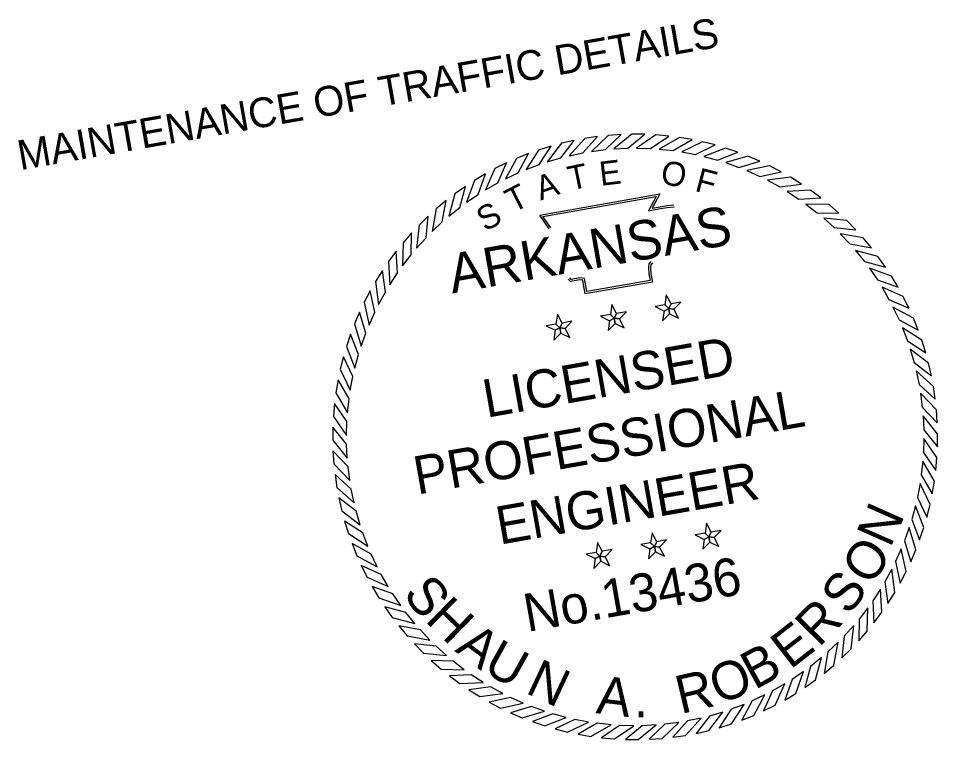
# Model space of a CAD drawing. Extents: x 986385 to 987873, y 1837463 to 1838653.
# Drawn here: x 987580 to 987761.3, y 1838510.4 to 1838652.5 of the extents above; entities that cross this region are included whole.
import ezdxf

# ---------------------------------------------------------------- set-up
doc = ezdxf.new("R2010")
doc.units = 0
doc.layers.add('1', color=7, linetype='Continuous')
doc.layers.add('G-ANNO-SYMB', color=7, linetype='Continuous')

msp = doc.modelspace()

# ---------------------------------------------------------------- linework, layer by layer
at = {"layer": 'G-ANNO-SYMB'}
for points in [[(987694.25, 1838629.23), (987691.71, 1838628.85), (987688.65, 1838625.45), (987691.37, 1838626.02)], [(987698.92, 1838629.62), (987696.36, 1838629.45), (987693.04, 1838626.3), (987695.79, 1838626.66)], [(987703.6, 1838629.66), (987701.04, 1838629.68), (987697.48, 1838626.81), (987700.25, 1838626.94)], [(987708.28, 1838629.32), (987705.72, 1838629.55), (987701.95, 1838626.96), (987704.72, 1838626.88)], [(987712.91, 1838628.62), (987710.38, 1838629.05), (987706.42, 1838626.76), (987709.17, 1838626.46)], [(987685.08, 1838627.34), (987682.63, 1838626.57), (987680.14, 1838622.74), (987682.73, 1838623.72)], [(987689.63, 1838628.46), (987687.13, 1838627.89), (987684.34, 1838624.26), (987687, 1838625.04)], [(987717.47, 1838627.56), (987714.98, 1838628.18), (987710.85, 1838626.21), (987713.58, 1838625.7)], [(987721.93, 1838626.14), (987719.5, 1838626.96), (987715.23, 1838625.32), (987717.91, 1838624.59)], [(987680.64, 1838625.86), (987678.26, 1838624.9), (987676.07, 1838620.88), (987678.58, 1838622.07)], [(987726.27, 1838624.38), (987723.91, 1838625.38), (987719.53, 1838624.08), (987722.14, 1838623.15)], [(987676.32, 1838624.04), (987674.02, 1838622.9), (987672.16, 1838618.72), (987674.57, 1838620.1)], [(987730.46, 1838622.28), (987728.19, 1838623.47), (987723.72, 1838622.52), (987726.24, 1838621.38)], [(987672.16, 1838621.88), (987669.96, 1838620.57), (987668.43, 1838616.26), (987670.72, 1838617.82)], [(987734.47, 1838619.86), (987732.3, 1838621.22), (987727.77, 1838620.62), (987730.2, 1838619.29)], [(987668.18, 1838619.41), (987666.09, 1838617.92), (987664.91, 1838613.51), (987667.07, 1838615.24)], [(987738.28, 1838617.13), (987736.22, 1838618.66), (987731.66, 1838618.42), (987733.98, 1838616.9)], [(987664.41, 1838616.63), (987662.44, 1838614.98), (987661.61, 1838610.49), (987663.63, 1838612.39)], [(987741.86, 1838614.11), (987739.93, 1838615.8), (987735.36, 1838615.92), (987737.55, 1838614.22)], [(987660.87, 1838613.56), (987659.04, 1838611.77), (987658.56, 1838607.22), (987660.42, 1838609.27)], [(987745.2, 1838610.82), (987743.4, 1838612.65), (987738.86, 1838613.13), (987740.91, 1838611.27)], [(987657.58, 1838610.23), (987655.89, 1838608.3), (987655.77, 1838603.72), (987657.47, 1838605.92)], [(987748.26, 1838607.28), (987746.62, 1838609.25), (987742.12, 1838610.08), (987744.03, 1838608.06)], [(987751.04, 1838603.51), (987749.56, 1838605.6), (987745.14, 1838606.78), (987746.88, 1838604.62)], [(987654.56, 1838606.65), (987653.03, 1838604.59), (987653.27, 1838600.02), (987654.79, 1838602.34)], [(987753.52, 1838599.53), (987752.2, 1838601.73), (987747.89, 1838603.26), (987749.45, 1838600.97)], [(987651.84, 1838602.84), (987650.47, 1838600.66), (987651.07, 1838596.13), (987652.4, 1838598.56)], [(987755.67, 1838595.37), (987754.53, 1838597.67), (987750.36, 1838599.53), (987751.73, 1838597.12)], [(987649.42, 1838598.83), (987648.23, 1838596.55), (987649.18, 1838592.08), (987650.31, 1838594.61)], [(987708.28, 1838595.32), (987708.74, 1838596.25), (987707.81, 1838598), (987707.53, 1838596.04)], [(987697.54, 1838593.42), (987698, 1838594.36), (987697.07, 1838596.11), (987696.79, 1838594.15)], [(987708.28, 1838595.32), (987707.53, 1838596.04), (987705.58, 1838595.7), (987707.36, 1838594.83)], [(987708.28, 1838595.32), (987709.31, 1838595.17), (987710.69, 1838596.6), (987708.74, 1838596.25)], [(987647.32, 1838594.64), (987646.31, 1838592.28), (987647.61, 1838587.89), (987648.54, 1838590.5)], [(987686.8, 1838591.53), (987687.25, 1838592.47), (987686.32, 1838594.22), (987686.05, 1838592.25)], [(987697.54, 1838593.42), (987696.79, 1838594.15), (987694.84, 1838593.8), (987696.62, 1838592.93)], [(987697.54, 1838593.42), (987698.57, 1838593.28), (987699.95, 1838594.7), (987698, 1838594.36)], [(987708.28, 1838595.32), (987707.36, 1838594.83), (987707.09, 1838592.87), (987708.46, 1838594.29)], [(987708.28, 1838595.32), (987708.46, 1838594.29), (987710.24, 1838593.42), (987709.31, 1838595.17)], [(987757.5, 1838591.06), (987756.54, 1838593.44), (987752.52, 1838595.62), (987753.71, 1838593.11)], [(987686.8, 1838591.53), (987686.05, 1838592.25), (987684.09, 1838591.91), (987685.88, 1838591.04)], [(987686.8, 1838591.53), (987687.83, 1838591.38), (987689.2, 1838592.81), (987687.25, 1838592.47)], [(987697.54, 1838593.42), (987696.62, 1838592.93), (987696.34, 1838590.97), (987697.72, 1838592.4)], [(987697.54, 1838593.42), (987697.72, 1838592.4), (987699.5, 1838591.53), (987698.57, 1838593.28)], [(987686.8, 1838591.53), (987685.88, 1838591.04), (987685.6, 1838589.08), (987686.98, 1838590.5)], [(987686.8, 1838591.53), (987686.98, 1838590.5), (987688.76, 1838589.63), (987687.83, 1838591.38)], [(987758.97, 1838586.61), (987758.21, 1838589.06), (987754.37, 1838591.55), (987755.36, 1838588.96)], [(987645.55, 1838590.3), (987644.73, 1838587.87), (987646.37, 1838583.6), (987647.1, 1838586.27)], [(987760.1, 1838582.06), (987759.53, 1838584.56), (987755.9, 1838587.35), (987756.68, 1838584.69)], [(987644.14, 1838585.83), (987643.51, 1838583.35), (987645.48, 1838579.22), (987645.99, 1838581.94)], [(987760.86, 1838577.44), (987760.49, 1838579.98), (987757.09, 1838583.04), (987757.66, 1838580.33)], [(987643.07, 1838581.27), (987642.64, 1838578.74), (987644.93, 1838574.78), (987645.23, 1838577.54)], [(987761.26, 1838572.77), (987761.09, 1838575.33), (987757.94, 1838578.65), (987758.29, 1838575.9)], [(987642.37, 1838576.64), (987642.14, 1838574.08), (987644.73, 1838570.32), (987644.81, 1838573.09)], [(987761.29, 1838568.09), (987761.32, 1838570.65), (987758.44, 1838574.21), (987758.58, 1838571.44)], [(987642.04, 1838571.97), (987642.01, 1838569.4), (987644.89, 1838565.85), (987644.75, 1838568.62)], [(987760.96, 1838563.42), (987761.19, 1838565.97), (987758.6, 1838569.74), (987758.51, 1838566.97)], [(987642.07, 1838567.28), (987642.24, 1838564.72), (987645.39, 1838561.41), (987645.04, 1838564.16)], [(987760.25, 1838558.79), (987760.68, 1838561.31), (987758.4, 1838565.27), (987758.1, 1838562.52)], [(987642.47, 1838562.62), (987642.84, 1838560.08), (987646.24, 1838557.02), (987645.67, 1838559.73)], [(987759.19, 1838554.22), (987759.82, 1838556.71), (987757.85, 1838560.84), (987757.34, 1838558.11)], [(987643.23, 1838557.99), (987643.8, 1838555.49), (987647.43, 1838552.71), (987646.65, 1838555.37)], [(987757.77, 1838549.76), (987758.59, 1838552.19), (987756.96, 1838556.46), (987756.23, 1838553.78)], [(987644.36, 1838553.45), (987645.12, 1838551), (987648.96, 1838548.51), (987647.97, 1838551.1)], [(987716.21, 1838550.33), (987716.67, 1838551.27), (987715.74, 1838553.02), (987715.47, 1838551.05)], [(987705.47, 1838548.44), (987705.93, 1838549.37), (987705, 1838551.12), (987704.72, 1838549.16)], [(987716.21, 1838550.33), (987715.47, 1838551.05), (987713.51, 1838550.71), (987715.3, 1838549.84)], [(987716.21, 1838550.33), (987717.25, 1838550.19), (987718.62, 1838551.61), (987716.67, 1838551.27)], [(987756.01, 1838545.42), (987757.02, 1838547.78), (987755.72, 1838552.16), (987754.79, 1838549.55)], [(987645.83, 1838549), (987646.79, 1838546.62), (987650.81, 1838544.44), (987649.62, 1838546.94)], [(987694.73, 1838546.54), (987695.18, 1838547.48), (987694.25, 1838549.23), (987693.98, 1838547.27)], [(987705.47, 1838548.44), (987704.72, 1838549.16), (987702.77, 1838548.82), (987704.55, 1838547.95)], [(987705.47, 1838548.44), (987706.5, 1838548.29), (987707.88, 1838549.72), (987705.93, 1838549.37)], [(987716.21, 1838550.33), (987715.3, 1838549.84), (987715.02, 1838547.88), (987716.4, 1838549.3)], [(987716.21, 1838550.33), (987716.4, 1838549.3), (987718.18, 1838548.44), (987717.25, 1838550.19)], [(987694.73, 1838546.54), (987693.98, 1838547.27), (987692.03, 1838546.92), (987693.81, 1838546.05)], [(987694.73, 1838546.54), (987695.76, 1838546.4), (987697.14, 1838547.82), (987695.18, 1838547.48)], [(987705.47, 1838548.44), (987704.55, 1838547.95), (987704.28, 1838545.98), (987705.65, 1838547.41)], [(987705.47, 1838548.44), (987705.65, 1838547.41), (987707.43, 1838546.54), (987706.5, 1838548.29)], [(987753.91, 1838541.23), (987755.1, 1838543.5), (987754.15, 1838547.98), (987753.02, 1838545.45)], [(987694.73, 1838546.54), (987693.81, 1838546.05), (987693.53, 1838544.09), (987694.91, 1838545.52)], [(987694.73, 1838546.54), (987694.91, 1838545.52), (987696.69, 1838544.65), (987695.76, 1838546.4)], [(987647.66, 1838544.69), (987648.79, 1838542.39), (987652.97, 1838540.53), (987651.59, 1838542.93)], [(987751.49, 1838537.22), (987752.86, 1838539.39), (987752.26, 1838543.93), (987750.93, 1838541.49)], [(987649.81, 1838540.53), (987651.13, 1838538.32), (987655.44, 1838536.8), (987653.87, 1838539.09)], [(987748.76, 1838533.41), (987750.3, 1838535.47), (987750.06, 1838540.04), (987748.54, 1838537.72)], [(987652.28, 1838536.55), (987653.77, 1838534.46), (987658.19, 1838533.27), (987656.45, 1838535.43)], [(987745.75, 1838529.83), (987747.43, 1838531.76), (987747.55, 1838536.33), (987745.86, 1838534.14)], [(987655.06, 1838532.78), (987656.71, 1838530.81), (987661.2, 1838529.97), (987659.3, 1838531.99)], [(987742.46, 1838526.49), (987744.29, 1838528.29), (987744.77, 1838532.84), (987742.91, 1838530.78)], [(987658.13, 1838529.24), (987659.92, 1838527.4), (987664.47, 1838526.92), (987662.42, 1838528.79)], [(987738.92, 1838523.43), (987740.88, 1838525.07), (987741.72, 1838529.57), (987739.7, 1838527.67)], [(987661.46, 1838525.95), (987663.4, 1838524.26), (987667.97, 1838524.14), (987665.77, 1838525.83)], [(987735.14, 1838520.65), (987737.24, 1838522.13), (987738.42, 1838526.55), (987736.26, 1838524.81)], [(987731.17, 1838518.17), (987733.37, 1838519.49), (987734.9, 1838523.8), (987732.61, 1838522.24)], [(987665.05, 1838522.93), (987667.11, 1838521.4), (987671.67, 1838521.64), (987669.35, 1838523.15)], [(987668.86, 1838520.2), (987671.03, 1838518.84), (987675.56, 1838519.43), (987673.13, 1838520.76)], [(987727.01, 1838516.02), (987729.31, 1838517.16), (987731.17, 1838521.34), (987728.76, 1838519.96)], [(987672.87, 1838517.78), (987675.14, 1838516.59), (987679.61, 1838517.54), (987677.08, 1838518.68)], [(987722.69, 1838514.2), (987725.07, 1838515.15), (987727.25, 1838519.17), (987724.75, 1838517.99)], [(987677.05, 1838515.68), (987679.41, 1838514.67), (987683.8, 1838515.97), (987681.19, 1838516.91)], [(987718.25, 1838512.72), (987720.69, 1838513.49), (987723.19, 1838517.32), (987720.59, 1838516.34)], [(987681.39, 1838513.92), (987683.83, 1838513.1), (987688.09, 1838514.74), (987685.42, 1838515.46)], [(987685.86, 1838512.5), (987688.35, 1838511.87), (987692.47, 1838513.84), (987689.75, 1838514.36)], [(987709.08, 1838510.83), (987711.62, 1838511.2), (987714.68, 1838514.6), (987711.96, 1838514.04)], [(987713.7, 1838511.6), (987716.2, 1838512.17), (987718.98, 1838515.79), (987716.32, 1838515.02)], [(987690.42, 1838511.44), (987692.95, 1838511.01), (987696.91, 1838513.29), (987694.16, 1838513.59)], [(987695.05, 1838510.74), (987697.61, 1838510.51), (987701.38, 1838513.1), (987698.61, 1838513.18)], [(987699.73, 1838510.4), (987702.29, 1838510.37), (987705.84, 1838513.25), (987703.08, 1838513.11)], [(987704.41, 1838510.43), (987706.97, 1838510.61), (987710.29, 1838513.75), (987707.54, 1838513.4)]]:
    msp.add_lwpolyline(points, close=True, dxfattribs=at)
for points in [[(987684.73, 1838611.01), (987682.84, 1838613.74), (987706.54, 1838617.93), (987704.99, 1838615.09), (987706.6, 1838615.4), (987707.94, 1838615.65), (987709.31, 1838615.74)], [(987685.05, 1838611.23), (987683.49, 1838613.46), (987705.82, 1838617.41), (987704.28, 1838614.57), (987706.67, 1838615.02), (987707.99, 1838615.27), (987709.34, 1838615.36)], [(987705.08, 1838604.36), (987704.73, 1838603.96), (987704.68, 1838603.44), (987704.77, 1838602.19), (987705.06, 1838600.55), (987691.83, 1838598.22), (987691.44, 1838600.43), (987691.35, 1838600.92), (987690.78, 1838600.99), (987688.9, 1838600.66), (987688.48, 1838601.11)], [(987704.79, 1838604.61), (987704.36, 1838604.11), (987704.3, 1838603.45), (987704.39, 1838602.15), (987704.61, 1838600.86), (987692.14, 1838598.66), (987691.81, 1838600.5), (987691.68, 1838601.27), (987690.77, 1838601.38), (987689.04, 1838601.07), (987688.76, 1838601.37)]]:
    msp.add_lwpolyline(points, dxfattribs=at)

# ---------------------------------------------------------------- texts
at = {"layer": '1'}
msp.add_text('MAINTENANCE OF TRAFFIC DETAILS', height=5.8625, rotation=10, dxfattribs=at).set_placement((987580.4, 1838622.58))
at = {"layer": 'G-ANNO-SYMB'}
for s, height, rotation, p in [('T', 4.75, 11.4789, (987688.88, 1838618.58)), ('E', 4.75, 6.672, (987694.88, 1838619.5)), ('O', 4.75, 351.2218, (987706.52, 1838619.89)), ('A', 4.75, 18.6788, (987683, 1838616.59)), ('F', 4.75, 345.3628, (987713.25, 1838618.54)), ('T', 4.75, 26.9015, (987677.59, 1838614.11)), ('S', 4.75, 29.7726, (987672.12, 1838610.39)), ('ARKANSAS', 7.747, 10, (987665.59, 1838598.27)), ('LICENSED', 7.5, 10, (987672.35, 1838573.79)), ('PROFESSIONAL', 7.5, 10, (987658.7, 1838558.65)), ('ENGINEER', 7.5, 10, (987674.95, 1838548.77)), ('N', 7.5, 66.1007, (987751.99, 1838548)), ('O', 7.5, 54.7757, (987748.04, 1838540.44)), ('No.13436', 7.47, 10, (987680.39, 1838531.58)), ('S', 7.5, 53.4878, (987743.83, 1838534.65)), ('S', 7.5, 308.1636, (987655.68, 1838538.97)), ('H', 7.5, 315.619, (987660.07, 1838533.78)), ('R', 7.5, 45.6597, (987737.92, 1838528.43)), ('E', 7.5, 37.8315, (987732.25, 1838524.06)), ('A', 7.5, 323.4472, (987665.95, 1838527.86)), ('U', 7.5, 330.9026, (987671.4, 1838523.86)), ('B', 7.5, 28.885, (987725.26, 1838520.08)), ('N', 7.5, 334.9326, (987679.81, 1838519.67)), ('O', 7.5, 21.4296, (987718.14, 1838517.2)), ('R', 7.5, 13.2287, (987710.66, 1838515.39)), ('A', 7.5, 353.0991, (987693.8, 1838515.6)), ('.', 7.5, 1.3, (987701.44, 1838514.73))]:
    msp.add_text(s, height=height, rotation=rotation, dxfattribs=at).set_placement(p)

doc.saveas('drawing.dxf')
